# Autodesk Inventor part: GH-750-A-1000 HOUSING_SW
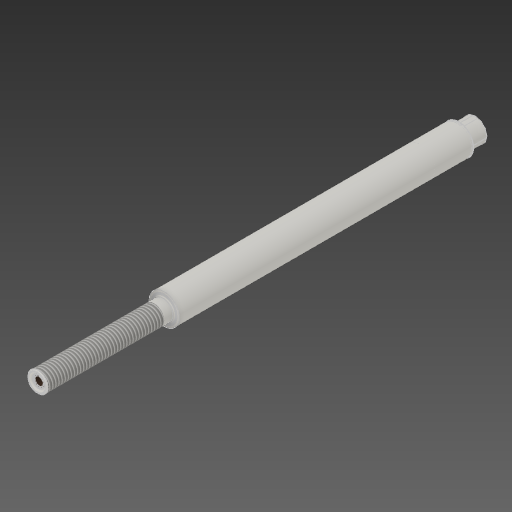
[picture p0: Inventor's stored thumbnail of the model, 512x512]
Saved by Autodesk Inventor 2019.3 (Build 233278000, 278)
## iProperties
Created: 2018-11
Part Number: GH-750-A-1000 HOUSING_SW
Material: Generic
Document SubType Name: Modeling
Designer: Justin
Density: 1 g/cm^3
Appearance: Default
Mass: 25.9896 g
Surface Area: 295.306 cm^2
Volume: 24.8188 cm^3
Author: Justin
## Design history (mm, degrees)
node "Assembly1"
body "Solid1"
node "Part1:1"
node "Part2:1"
body "Solid2"
node "Part3:1"
body "Solid3"
node "Part4:1"
body "Solid4"
node "Part5:1"
body "Solid5"
